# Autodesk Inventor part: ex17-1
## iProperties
Created: 2006-04
Part Number: ex17-1
Project: EVERGREEN VALLEY COLLEGE
Description: U-JOINT
Document SubType Name: Modeling
Designer: E. MOSS
Authority: MS. TEACHER
Author: E. MOSS
Revision Number: A
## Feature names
1. Sweep1
2. Revolution1
3. Mirror1
4. Hole1
5. Extrusion1
6. Fillet1
